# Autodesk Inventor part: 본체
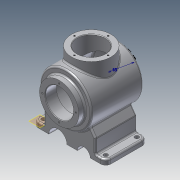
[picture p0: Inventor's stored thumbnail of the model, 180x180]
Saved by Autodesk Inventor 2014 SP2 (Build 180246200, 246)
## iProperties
Created: 2018-08
Part Number: 본체
Material: 알루미늄 6061
Document SubType Name: Modeling
Designer: 거성
Density: 2.71 g/cm^3
Appearance: 알루미늄 - 평지
Mass: 1903.75 g
Surface Area: 1094.31 cm^2
Volume: 702.492 cm^3
Author: 거성
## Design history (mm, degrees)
sketch "스케치1"
  geometry: L1 (0, 60)-(0, -60); L2 (0, 60)-(38, 60); L3 (38, 60)-(38, 48); L4 (38, 48)-(50, 48); L5 (50, 48)-(50, -52); A1 r 232 centre (-11.435, 171.718) between (0, -60) and (50, -52); 2 further points
  constraints: 10 end point, 3 perpendicular, 2 point on circle, 1 centre point, 1 coincident, 1 midpoint, 1 parallel, 1 vertical
  dimensions: "d0" = 120 distance of L1.start L1.end; "d2" = 76 diameter of L3 L1; "d4" = 12 distance of L2.end L3.end; "d22" = 100 distance of L4.end L5.end; "d23" = 232 radius of A1; "d24" = 100 diameter of L5 L1
revolve "회전1" sketch "스케치1" stored, may be unused: angle "d6" = 90 deg
sketch "스케치2" dims "d8" = 65
  geometry: C1 r 38 at (0, 0) reference; C2 r 27 at (0, 0); 2 further points
  constraints: 2 coincident, 2 vertical alignment, 1 centre point, 2 other
  dimensions: "d7" = 54 diameter of C2
extrude "돌출1" cut sketch "스케치2" distance "d9" = 22; taper "d10" = 0 deg
hole "구멍1" sketch "스케치2" diameter "d11" = 3.242; stored, may be unused: countersink angle "d15" = 90 deg, drill point angle "d17" = 118 deg; dims "d12" = 8, "d13" = 4, "d14" = 2, "d16" = 10
node "작업 평면1"
sketch "스케치3"
  geometry: L1 (50, 48)-(50, -52) reference; L2 (-50, -52)-(50, -52) reference; L3 (-50, -52)-(50, -52) reference; L4 (-50, 48)-(-50, -52) reference; L5 (0, -49.674)-(0, 38.326); L6 (0, 38.326)-(40, 38.326); L7 (40, 38.326)-(40, -43.225); A1 r 232 centre (-11.435, 171.718) between (0, -60) and (50, -52) reference; A2 r 232 centre (11.435, 171.718) between (-50, -52) and (0, -60) reference; A3 r 232 centre (-16.787, 181.718) between (0, -49.674) and (40, -43.225); 3 further points
  constraints: 6 end point, 2 point on circle, 1 centre point, 1 coincident, 1 perpendicular
  dimensions: "d89" = 88 distance of L5.start L5.end; "d91" = 232 radius of A3; "d92" = 10 vertical distance of A1.centre A3.centre; "d108" = 80 diameter of L7 L5
  node "투영된 루프1"
node "작업 평면2"
sketch "스케치4" dims "d31" = 65
  geometry: L1 (-50, 48)-(50, 48) reference; C1 r 38 at (0, -2); C2 r 27 at (0, -2); 2 further points
  constraints: 2 centre point, 2 coincident, 1 vertical alignment, 2 other
  dimensions: "d30" = 76 diameter of C1; "d32" = 54 diameter of C2; "d107" = 50 distance from line of L1 C1.centre
extrude "돌출2" join sketch "스케치4" stored distance "d33" = 22; taper "d34" = 0 deg
extrude "돌출3" cut sketch "스케치4" distance "d35" = 50; taper "d36" = 0 deg
hole "구멍2" sketch "스케치4" diameter "d37" = 3.242; stored, may be unused: countersink angle "d41" = 90 deg, drill point angle "d43" = 118 deg; dims "d38" = 8, "d39" = 4, "d40" = 2, "d42" = 10
node "작업 평면3"
sketch "스케치5"
  geometry: L1 (-39.739, -30.345)-(-50, -45); L2 (-50, -45)-(-50, -72); L3 (-50, -72)-(-70, -72); L4 (-70, -72)-(-70, -82); L5 (70, -82)-(70, -72); L6 (70, -72)-(50, -72); L7 (50, -72)-(50, -45); L8 (50, -45)-(39.739, -30.345); L9 (-70, -82)-(-40, -82); L10 (-15, -82)-(5, -82); L11 (40, -82)-(70, -82); C1 r 38 at (0, 0) reference; A1 r 50 centre (0, 0) between (-39.739, -30.345) and (39.739, -30.345) reference; A2 r 12.5 centre (-27.5, -82) between (-15, -82) and (-40, -82); A3 r 17.5 centre (22.5, -82) between (40, -82) and (5, -82); 5 further points
  constraints: 22 end point, 9 perpendicular, 6 point on circle, 3 midpoint, 2 centre point, 2 horizontal alignment, 2 parallel, 1 point on line, 1 vertical, 1 vertical alignment
  dimensions: "d48" = 35 deg angle of L1 L4; "d50" = 20 distance of L2.end L3.end; "d52" = 10 distance of L3.end L4.end; "d61" = 140 distance of L4.end L5.start; "d62" = 20 distance of L5.end L6.end; "d63" = 10 distance of L5.start L5.end; "d64" = 35 deg angle of L5 L8; "d65" = 25 diameter of A2; "d66" = 35 diameter of A3; "d67" = 27.5 distance of point (0, -82) A2.centre; "d68" = 22.5 distance of point (0, -82) A3.centre; "d69" = 27 distance of L1.end L2.end; "d70" = 82 distance from line of C1.centre L9; "d71" = 42.5 distance of L4.end A2.centre; "d72" = 47.5 distance of L5.start A3.centre; "d73" = 22.5 distance of A2.centre point (-5, -82)
extrude "돌출4" join sketch "스케치5" stored distance "d75" = 80; taper "d76" = 0 deg
node "작업 평면4"
sketch "스케치6"
  geometry: C1 r 32.5 at (0, 0); 1 further point
  constraints: 1 centre point, 1 coincident, 1 other
  dimensions: "d78" = 65 diameter of C1
fillet "모깎기1" dims "d79" = 3
fillet "모깎기2" dims "d80" = 3
fillet "모깎기3" dims "d81" = 3
fillet "모깎기5" dims "d83" = 10
fillet "모깎기6" dims "d84" = 10
node "작업 평면5"
sketch "스케치7"
  geometry: L1 (38, -38)-(-38, -38) reference; 1 further point
revolve "회전3" stored, may be unused: angle "d93" = 90 deg
fillet "모깎기8" dims "d94" = 3
chamfer "모따기1" distance "d95" = 1; stored, may be unused: second distance "d96" = 2, angle "d97" = 45 deg
node "작업 평면7"
sketch "스케치8"
  geometry: C1 r 4 at (0, 7); C2 r 4 at (0, 67); A1 r 7 centre (0, 67) between (0, 74) and (-7, 67) reference; A2 r 7 centre (0, 7) between (-7, 7) and (0, 0) reference; 1 further point
  constraints: 2 centre point, 2 coincident
  dimensions: "d98" = 8 diameter of C1; "d99" = 8 diameter of C2
extrude "돌출5" cut sketch "스케치8" stored distance "d100" = 80; taper "d101" = 0 deg
node "작업 평면6"
sketch "스케치9"
  geometry: C1 r 4 at (10, -7); C2 r 4 at (10, -67); A1 r 7 centre (10, -67) between (10, -74) and (17, -67) reference; A2 r 7 centre (10, -7) between (17, -7) and (10, 0) reference; 1 further point
  constraints: 2 centre point, 2 coincident
  dimensions: "d102" = 8 diameter of C1; "d103" = 8 diameter of C2
extrude "돌출6" cut sketch "스케치9" distance "d104" = 80; taper "d105" = 0 deg
fillet "모깎기9" dims "d106" = 3
node "솔리드1"
pattern_circular "원형 패턴1" dims angle "d19" = 360 deg
pattern_circular "원형 패턴2" dims angle "d45" = 360 deg
node "투영된 루프2"
other parameters: "d25" = 0, "d29" = 65, "d47" = 0, "d60" = 82, "d86" = 0
